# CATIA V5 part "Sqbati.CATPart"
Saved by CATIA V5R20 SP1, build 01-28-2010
Part number: Sqbati
Publications: "Droite.1", "Plan.1", "Droite.2", "Droite.3"
Bounding box of the stored display mesh (mm): x -20 to 140, y 0 to 132.555, z -287.997 to 0
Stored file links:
  C:\Users\RENARD Simon\Documents\Cours IFMA\2ème année\IAO\Sqbati.CATPart
  C:\Users\RENARD Simon\Documents\Cours IFMA\2ème année\IAO\Trainattero.CATProduct
  C:\Users\RENARD Simon\Documents\Cours IFMA\2ème année\IAO\Sqpiece1.CATPart
  C:\Users\RENARD Simon\Documents\Cours IFMA\2ème année\IAO\Sqpiece3.CATPart
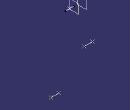
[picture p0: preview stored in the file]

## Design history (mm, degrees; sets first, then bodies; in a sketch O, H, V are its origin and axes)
Set1
  DatumPoint1 to DatumPoint4: linked copy from another document
Body1 (main body)
  Point1: (0, 0, 0)
  Line1: type Normal, RefPoint Point1, RefSkin yz-plane, Start -20, End 20
  Plane1: type OffsetPt, RefPlane yz-plane, RefPoint vertex of Line1
  Line2: type PtPt, FirstPoint DatumPoint1, SecondPoint DatumPoint2
  Line3: type PtPt, FirstPoint DatumPoint3, SecondPoint DatumPoint4
  Plane2: type Offset, RefPlane Plane1, Offset 40, reversed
